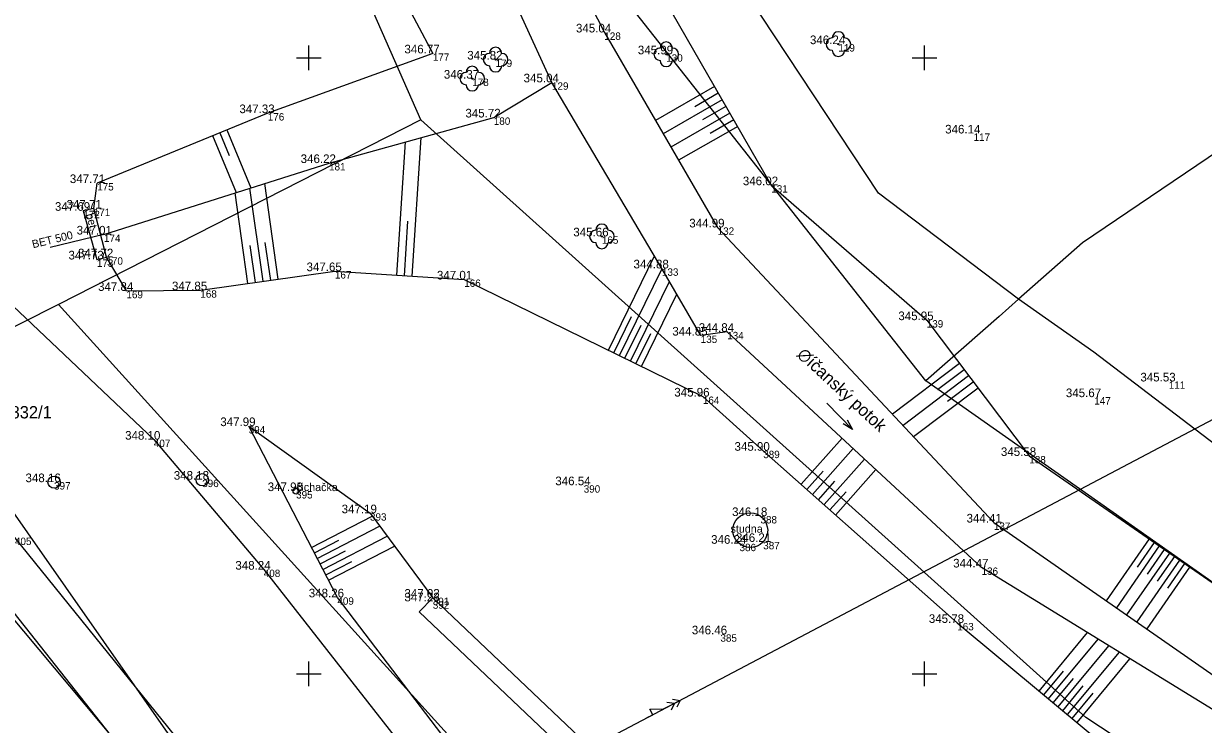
# Model space of a CAD drawing. Extents: x -614046 to -613877, y -1156755 to -1156623.
# Drawn here: x -614009.26 to -613970.95, y -1156701.64 to -1156678.89 of the extents above; entities that cross this region are included whole.
import ezdxf

# ---------------------------------------------------------------- set-up
doc = ezdxf.new("R2010")
doc.units = 0
for name, color, linetype in [('1-bod', 7, 'Continuous'), ('10-silnice', 7, 'Continuous'), ('11-zpevněné plochy', 7, 'Continuous'), ('14-terénní hrany', 7, 'Continuous'), ('15-šrafy', 7, 'Continuous'), ('16-vodní tok', 7, 'Continuous'), ('2-bod výška', 7, 'Continuous'), ('22-stromy', 7, 'Continuous'), ('27-kanalizace značky', 7, 'Continuous'), ('3-bod číslo', 7, 'Continuous'), ('31-plynovod značky', 7, 'Continuous'), ('32-elekrické vedení', 7, 'Continuous'), ('40-popisy povrchů', 7, 'Continuous'), ('45-popis vodní tok', 7, 'Continuous'), ('50-hranice parcel KN', 7, 'Continuous'), ('61-hektarová síť', 7, 'Continuous'), ('7-plot', 7, 'Continuous')]:
    doc.layers.add(name, color=color, linetype=linetype)

# ---------------------------------------------------------------- blocks, each defined once
blk = doc.blocks.new('3.13_1')
at = {"layer": '22-stromy'}
blk.add_circle((0, 0), 0.05, dxfattribs=at)
for centre, start, end in [((0, 0.5), 0, 180), ((-0.5, 0), 90, 270), ((0.5, 0), 270, 90), ((0, -0.5), 180, 0)]:
    blk.add_arc(centre, 0.5, start, end, dxfattribs=at)
blk = doc.blocks.new('6.20_1')
at = {"layer": '27-kanalizace značky'}
blk.add_circle((0, 0), 0.5, dxfattribs=at)
blk = doc.blocks.new('8.02')
at = {"layer": '45-popis vodní tok'}
blk.add_line((-3, 0), (0, 0), dxfattribs=at)
blk.add_lwpolyline([(-0.876, 0.23), (0, 0), (-0.876, -0.23)], dxfattribs=at)
blk = doc.blocks.new('6.14B_1')
at = {"layer": '31-plynovod značky'}
blk.add_circle((0, 0), 0.25, dxfattribs=at)
blk = doc.blocks.new('6.61_1')
at = {"layer": '32-elekrické vedení'}
for points in [[(-3, 0), (-2.5, 0), (-2.5, 0.5), (-1.5, 0), (0, 0)], [(-1, 0.375), (-0.5, 0), (-1, -0.375)], [(-0.5, 0.375), (0, 0), (-0.5, -0.375)]]:
    blk.add_lwpolyline(points, dxfattribs=at)
blk = doc.blocks.new('POINT_DISPLAY')
blk.add_line((0, 0), (0, 0))

msp = doc.modelspace()

# ---------------------------------------------------------------- linework, layer by layer
at = {"layer": '10-silnice'}
for points in [[(-614040.86, -1156670.12), (-614026.04, -1156676.19), (-614020.49, -1156678.89), (-614017.81, -1156680.62), (-614014.97, -1156682.84), (-614010.02, -1156687.67), (-614005.03, -1156692.4), (-614001.46, -1156696.62), (-613996.56, -1156702.86), (-613991.22, -1156709.86), (-613982.03, -1156721.02), (-613980.56, -1156722.02), (-613978.09, -1156724.42), (-613976.34, -1156726.49), (-613975.01, -1156727.5), (-613973.5, -1156728.21), (-613971.99, -1156728.45), (-613970.47, -1156728.44), (-613968.47, -1156728.24), (-613968.3, -1156728.73), (-613958.25, -1156725.06), (-613953.29, -1156723.55)], [(-613998.81, -1156737.86), (-613991.24, -1156735.67), (-613989.47, -1156735.13), (-613988.16, -1156734.5), (-613987.29, -1156733.62), (-613986.54, -1156732.34), (-613986.06, -1156731.07), (-613985.73, -1156729.66), (-613985.61, -1156728.49), (-613985.69, -1156727.41), (-613986.15, -1156725.89), (-613987.36, -1156723.48), (-613995.06, -1156713.22), (-614002.8, -1156703.92), (-614009.54, -1156695.58), (-614011.63, -1156693.4), (-614020.17, -1156685.74), (-614023.41, -1156683.58), (-614026.53, -1156682.03), (-614044.45, -1156674.63)]]:
    msp.add_lwpolyline(points, dxfattribs=at)
at = {"layer": '11-zpevněné plochy'}
msp.add_line((-614006.57, -1156686.48), (-614006.98, -1156684.9), dxfattribs=at)
for points in [[(-614006.98, -1156684.9), (-614007.32, -1156684.97), (-614006.88, -1156686.55), (-614006.57, -1156686.48)], [(-614006.65, -1156685.74), (-614008.401, -1156686.16)]]:
    msp.add_lwpolyline(points, dxfattribs=at)
msp.add_circle((-613985.66, -1156695.34), 0.564, dxfattribs=at)
at = {"layer": '14-terénní hrany'}
for p, q in [((-613993.99, -1156681.94), (-613992.1, -1156680.8)), ((-613999.34, -1156683.42), (-613993.99, -1156681.94)), ((-614006.65, -1156685.74), (-613999.34, -1156683.42)), ((-614006.98, -1156684.9), (-614006.87, -1156684.07)), ((-614005.92, -1156687.57), (-614006.57, -1156686.48)), ((-613998.01, -1156694.79), (-613995.97, -1156697.53))]:
    msp.add_line(p, q, dxfattribs=at)
for points in [[(-614004.4, -1156659.13), (-614004.3, -1156663.09), (-614002.61, -1156666.66), (-614001.67, -1156667.48), (-614000.1, -1156670.92), (-613999.15, -1156673.88), (-613995.97, -1156679.86), (-614001.33, -1156681.8), (-614006.87, -1156684.07)], [(-613997.04, -1156660.09), (-613993.56, -1156668.05), (-613988.66, -1156677.73), (-613984.98, -1156684.14), (-613979.93, -1156688.52), (-613976.6, -1156692.93), (-613968.24, -1156698.72), (-613963.28, -1156701.99), (-613959.08, -1156705.39), (-613955.46, -1156707.77), (-613951.07, -1156711.08), (-613944.86, -1156716.28)], [(-614005.92, -1156687.57), (-614003.52, -1156687.55), (-613999.15, -1156686.93), (-613994.95, -1156687.2), (-613987.2, -1156691), (-613985.24, -1156692.76), (-613978.94, -1156698.35), (-613973.2, -1156703.12), (-613965.66, -1156708.33)], [(-613957.9, -1156720.91), (-613960.99, -1156718.37), (-613971.77, -1156722.19), (-613979.82, -1156720.78), (-613982.37, -1156717.47), (-613989.67, -1156708.83), (-613995.3, -1156702.47), (-613999.07, -1156697.52), (-614001.95, -1156691.96)], [(-614001.95, -1156691.96), (-613998.01, -1156694.79)]]:
    msp.add_lwpolyline(points, dxfattribs=at)
at = {"layer": '15-šrafy'}
for p, q in [((-613986.82, -1156680.93), (-613988.74, -1156682.04)), ((-613986.57, -1156681.37), (-613988.49, -1156682.47)), ((-613986.7, -1156681.15), (-613987.46, -1156681.59)), ((-613986.32, -1156681.8), (-613988.24, -1156682.9)), ((-613986.45, -1156681.58), (-613987.21, -1156682.02)), ((-613986.07, -1156682.23), (-613987.99, -1156683.33)), ((-613986.2, -1156682.02), (-613986.96, -1156682.46)), ((-614003.12, -1156682.53), (-614002.36, -1156684.38)), ((-614002.89, -1156682.44), (-614002.58, -1156683.18)), ((-614002.66, -1156682.34), (-614001.88, -1156684.23)), ((-613996.64, -1156687.09), (-613996.35, -1156682.59)), ((-613997.14, -1156687.06), (-613996.86, -1156682.73)), ((-614000.99, -1156687.19), (-614001.43, -1156684.08)), ((-614001.98, -1156687.33), (-614002.39, -1156684.39)), ((-614001.48, -1156687.26), (-614001.91, -1156684.24)), ((-613996.89, -1156687.08), (-613996.78, -1156685.31)), ((-614001.73, -1156687.3), (-614001.9, -1156686.1)), ((-614001.23, -1156687.23), (-614001.41, -1156686)), ((-613990.27, -1156689.495), (-613988.769, -1156686.435)), ((-613989.911, -1156689.671), (-613988.526, -1156686.847)), ((-613989.552, -1156689.847), (-613988.285, -1156687.264)), ((-613989.192, -1156690.023), (-613988.044, -1156687.681)), ((-613990.09, -1156689.583), (-613989.513, -1156688.406)), ((-613989.731, -1156689.759), (-613989.201, -1156688.678)), ((-613989.372, -1156689.935), (-613988.889, -1156688.95)), ((-613978.87, -1156689.93), (-613981.04, -1156691.57)), ((-613978.57, -1156690.33), (-613980.7, -1156691.94)), ((-613978.72, -1156690.13), (-613979.58, -1156690.78)), ((-613978.42, -1156690.53), (-613979.26, -1156691.16)), ((-613978.26, -1156690.73), (-613980.36, -1156692.31)), ((-613984.01, -1156693.85), (-613982.68, -1156692.35)), ((-613983.64, -1156694.18), (-613982.32, -1156692.69)), ((-613983.26, -1156694.51), (-613981.95, -1156693.03)), ((-613982.89, -1156694.85), (-613981.58, -1156693.37)), ((-613983.82, -1156694.02), (-613983.29, -1156693.42)), ((-613983.45, -1156694.35), (-613982.92, -1156693.75)), ((-613983.08, -1156694.68), (-613982.55, -1156694.09)), ((-613999.909, -1156695.9), (-613997.942, -1156694.881)), ((-613999.725, -1156696.255), (-613997.7, -1156695.206)), ((-613999.817, -1156696.078), (-613999.019, -1156695.664)), ((-613999.541, -1156696.611), (-613997.458, -1156695.532)), ((-613972.709, -1156695.625), (-613974.098, -1156697.629)), ((-613999.633, -1156696.433), (-613998.811, -1156696.007)), ((-613999.357, -1156696.966), (-613997.216, -1156695.857)), ((-613972.38, -1156695.852), (-613973.769, -1156697.858)), ((-613972.051, -1156696.08), (-613973.441, -1156698.086)), ((-613972.545, -1156695.739), (-613973.1, -1156696.541)), ((-613972.216, -1156695.966), (-613972.771, -1156696.769)), ((-613999.449, -1156696.788), (-613998.604, -1156696.351)), ((-613971.723, -1156696.308), (-613973.112, -1156698.314)), ((-613971.887, -1156696.194), (-613972.443, -1156696.997)), ((-613971.558, -1156696.422), (-613972.114, -1156697.225)), ((-613971.394, -1156696.536), (-613972.784, -1156698.543)), ((-613976.281, -1156700.56), (-613974.707, -1156698.666)), ((-613975.973, -1156700.815), (-613974.363, -1156698.877)), ((-613975.666, -1156701.071), (-613974.018, -1156699.089)), ((-613975.358, -1156701.327), (-613973.674, -1156699.3)), ((-613975.05, -1156701.582), (-613973.33, -1156699.512)), ((-613976.127, -1156700.687), (-613975.49, -1156699.921)), ((-613975.82, -1156700.943), (-613975.168, -1156700.159)), ((-613975.512, -1156701.199), (-613974.846, -1156700.397)), ((-613975.204, -1156701.454), (-613974.523, -1156700.635))]:
    msp.add_line(p, q, dxfattribs=at)
at = {"layer": '16-vodní tok'}
for points in [[(-614001.52, -1156651.1), (-613998.11, -1156660.56), (-613996.01, -1156668.21), (-613990.4, -1156679.18), (-613986.72, -1156685.51), (-613977.75, -1156695.09), (-613969.35, -1156700.93), (-613963.95, -1156705.16), (-613955.95, -1156708.89), (-613951.7, -1156712.2), (-613945.56, -1156718.87), (-613945.478, -1156720.252)], [(-613947.4, -1156720.89), (-613951.41, -1156714.98), (-613956.19, -1156710.22), (-613963.8, -1156706.47), (-613969.59, -1156701.81), (-613978.15, -1156696.55), (-613986.41, -1156688.9), (-613987.27, -1156689.02), (-613988.53, -1156686.84), (-613992.1, -1156680.8), (-613997.89, -1156668.2), (-613999.34, -1156662.5), (-614003.52, -1156652.97)]]:
    msp.add_lwpolyline(points, dxfattribs=at)
at = {"layer": '32-elekrické vedení'}
for points in [[(-613977.94, -1156741.03), (-614000.64, -1156707.56), (-614022.4, -1156676.44), (-614038.357, -1156667.025)], [(-614000.64, -1156707.56), (-613951.83, -1156681.82)]]:
    msp.add_lwpolyline(points, dxfattribs=at)
at = {"layer": '50-hranice parcel KN'}
for points in [[(-613996.36, -1156682.02), (-614004.36, -1156663.86)], [(-613981.5, -1156684.4), (-613992.03, -1156668.46)], [(-613979.96, -1156690.49), (-613994.87, -1156671.57)], [(-613955.27, -1156672.74), (-613974.87, -1156686.01)], [(-613996.36, -1156682.02), (-614008.13, -1156688.01)], [(-613974.76, -1156701.42), (-613996.36, -1156682.02)], [(-613976.95, -1156687.84), (-613981.5, -1156684.4)], [(-613974.87, -1156686.01), (-613976.95, -1156687.84)], [(-614008.13, -1156688.01), (-614010.58, -1156689.25)], [(-614008.13, -1156688.01), (-613987.63, -1156710.64)], [(-613976.95, -1156687.84), (-613977.58, -1156688.4)], [(-613974.5, -1156689.56), (-613976.95, -1156687.84)], [(-613977.58, -1156688.4), (-613979.96, -1156690.49)], [(-613943.81, -1156712.94), (-613974.5, -1156689.56)], [(-613947.86, -1156713.04), (-613979.96, -1156690.49)], [(-614013.75, -1156693.26), (-614005.78, -1156702.78)], [(-613954.79, -1156714.58), (-613974.76, -1156701.42)]]:
    msp.add_lwpolyline(points, dxfattribs=at)
at = {"layer": '61-hektarová síť'}
for points in [[(-614000, -1156680.4), (-614000, -1156680), (-614000, -1156679.6)], [(-613980, -1156680.4), (-613980, -1156680), (-613980, -1156679.6)], [(-614000.4, -1156680), (-614000, -1156680), (-613999.6, -1156680)], [(-613980.4, -1156680), (-613980, -1156680), (-613979.6, -1156680)], [(-614000, -1156700.4), (-614000, -1156700), (-614000, -1156699.6)], [(-613980, -1156700.4), (-613980, -1156700), (-613980, -1156699.6)], [(-614000.4, -1156700), (-614000, -1156700), (-613999.6, -1156700)], [(-613980.4, -1156700), (-613980, -1156700), (-613979.6, -1156700)]]:
    msp.add_lwpolyline(points, dxfattribs=at)
at = {"layer": '7-plot'}
for points in [[(-614025.62, -1156687.36), (-614021.23, -1156686.11), (-614012.67, -1156694.12), (-614005.8, -1156702.8), (-613992.19, -1156725.24), (-613995.31, -1156726.13)], [(-613996.41, -1156697.99), (-613995.97, -1156697.53)], [(-613995.97, -1156697.53), (-613982.98, -1156709.87), (-613978.43, -1156714.12), (-613972.48, -1156720.16)], [(-613996.41, -1156697.99), (-613983.42, -1156710.33), (-613978.87, -1156714.58), (-613972.93, -1156720.61)]]:
    msp.add_lwpolyline(points, dxfattribs=at)

# ---------------------------------------------------------------- block references
at = {"layer": '1-bod'}
for p in [(-613990.4, -1156679.18), (-613982.8, -1156679.56), (-613995.97, -1156679.86), (-613988.39, -1156679.89), (-613993.93, -1156680.06), (-613994.69, -1156680.68), (-613992.1, -1156680.8), (-614001.33, -1156681.8), (-613993.99, -1156681.94), (-613978.41, -1156682.46), (-613999.34, -1156683.42), (-614006.87, -1156684.07), (-613984.98, -1156684.14), (-614007.32, -1156684.97), (-614006.98, -1156684.9), (-614006.65, -1156685.74), (-613986.72, -1156685.51), (-613990.48, -1156685.8), (-614006.57, -1156686.48), (-614006.88, -1156686.55), (-613988.53, -1156686.84), (-613999.15, -1156686.93), (-613994.95, -1156687.2), (-614005.92, -1156687.57), (-614003.52, -1156687.55), (-613979.93, -1156688.52), (-613987.27, -1156689.02), (-613986.41, -1156688.9), (-613972.07, -1156690.51), (-613987.2, -1156691), (-613974.49, -1156691.02), (-614001.95, -1156691.96), (-614005.03, -1156692.4), (-613985.24, -1156692.76), (-613976.6, -1156692.93), (-614008.27, -1156693.78), (-614003.46, -1156693.7), (-614000.41, -1156694.07), (-613991.07, -1156693.88), (-613998.01, -1156694.79), (-613985.33, -1156694.88), (-613977.75, -1156695.09), (-613986.01, -1156695.78), (-613985.24, -1156695.72), (-614001.46, -1156696.62), (-613978.15, -1156696.55), (-613999.07, -1156697.52), (-613995.97, -1156697.53), (-613995.97, -1156697.65), (-613978.94, -1156698.35), (-613986.63, -1156698.72)]:
    msp.add_blockref('POINT_DISPLAY', p, dxfattribs=at)
at = {"layer": '22-stromy', "xscale": 0.4, "yscale": 0.4000000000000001}
for p in [(-613982.8, -1156679.56), (-613988.39, -1156679.89), (-613993.93, -1156680.06), (-613994.69, -1156680.68), (-613990.48, -1156685.8)]:
    msp.add_blockref('3.13_1', p, dxfattribs=at)
at = {"layer": '27-kanalizace značky', "xscale": 0.4, "yscale": 0.4000000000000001}
for p in [(-614008.27, -1156693.78), (-614003.46, -1156693.7)]:
    msp.add_blockref('6.20_1', p, dxfattribs=at)
at = {"layer": '31-plynovod značky', "xscale": 0.4, "yscale": 0.4000000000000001}
msp.add_blockref('6.14B_1', (-614000.41, -1156694.07), dxfattribs=at)
at = {"layer": '32-elekrické vedení', "xscale": 0.4, "yscale": 0.4000000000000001, "rotation": 27.804965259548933}
msp.add_blockref('6.61_1', (-613987.943, -1156700.864), dxfattribs=at)
at = {"layer": '45-popis vodní tok', "xscale": 0.39999999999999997, "yscale": 0.39999999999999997, "rotation": -45.60628191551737}
msp.add_blockref('8.02', (-613982.337, -1156692.068), dxfattribs=at)

# ---------------------------------------------------------------- texts
at = {"layer": '2-bod výška'}
for s, p in [('345.04 ', (-613991.322, -1156679.18)), ('346.77 ', (-613996.892, -1156679.86)), ('345.99 ', (-613989.312, -1156679.89)), ('346.24 ', (-613983.722, -1156679.56)), ('345.82 ', (-613994.852, -1156680.06)), ('346.37 ', (-613995.612, -1156680.68)), ('345.04 ', (-613993.022, -1156680.8)), ('347.33 ', (-614002.252, -1156681.8)), ('345.72 ', (-613994.912, -1156681.94)), ('346.14 ', (-613979.332, -1156682.46)), ('346.22 ', (-614000.262, -1156683.42)), ('347.71 ', (-614007.757, -1156684.07)), ('346.02 ', (-613985.902, -1156684.14)), ('347.69 ', (-614008.242, -1156684.97)), ('347.71 ', (-614007.867, -1156684.9)), ('344.99 ', (-613987.642, -1156685.51)), ('347.01 ', (-614007.537, -1156685.74)), ('345.66 ', (-613991.408, -1156685.8)), ('347.73 ', (-614007.802, -1156686.55)), ('347.72 ', (-614007.492, -1156686.48)), ('347.65 ', (-614000.072, -1156686.93)), ('344.88 ', (-613989.452, -1156686.84)), ('347.85 ', (-614004.442, -1156687.55)), ('347.01 ', (-613995.837, -1156687.2)), ('347.84 ', (-614006.842, -1156687.57)), ('345.95 ', (-613980.852, -1156688.52)), ('344.85 ', (-613988.192, -1156689.02)), ('344.84 ', (-613987.332, -1156688.9)), ('345.53 ', (-613972.992, -1156690.51)), ('345.96 ', (-613988.128, -1156691)), ('345.67 ', (-613975.412, -1156691.02)), ('347.99 ', (-614002.872, -1156691.96)), ('348.10 ', (-614005.963, -1156692.4)), ('345.90 ', (-613986.173, -1156692.76)), ('345.58 ', (-613977.522, -1156692.93)), ('348.16 ', (-614009.198, -1156693.78)), ('348.18 ', (-614004.382, -1156693.7)), ('347.98 ', (-614001.332, -1156694.07)), ('346.54 ', (-613991.992, -1156693.88)), ('347.19 ', (-613998.932, -1156694.79)), ('346.18 ', (-613986.252, -1156694.88)), ('344.41 ', (-613978.637, -1156695.09)), ('346.24 ', (-613986.932, -1156695.78)), ('346.21 ', (-613986.127, -1156695.72)), ('348.24 ', (-614002.382, -1156696.62)), ('344.47 ', (-613979.072, -1156696.55)), ('348.26 ', (-613999.998, -1156697.52)), ('347.02 ', (-613996.892, -1156697.53)), ('347.23 ', (-613996.892, -1156697.65)), ('345.78 ', (-613979.862, -1156698.35)), ('346.46 ', (-613987.558, -1156698.72))]:
    msp.add_text(s, height=0.28, dxfattribs=at).set_placement(p)
at = {"layer": '3-bod číslo'}
for s, p in [('128', (-613990.4, -1156679.42)), ('119', (-613982.8, -1156679.8)), ('177', (-613995.97, -1156680.1)), ('130', (-613988.39, -1156680.13)), ('179', (-613993.93, -1156680.3)), ('178', (-613994.69, -1156680.92)), ('129', (-613992.1, -1156681.04)), ('176', (-614001.33, -1156682.04)), ('180', (-613993.99, -1156682.18)), ('117', (-613978.41, -1156682.7)), ('181', (-613999.34, -1156683.66)), ('175', (-614006.87, -1156684.31)), ('131', (-613984.98, -1156684.38)), ('172', (-614007.32, -1156685.21)), ('171', (-614006.98, -1156685.14)), ('174', (-614006.65, -1156685.98)), ('132', (-613986.72, -1156685.75)), ('165', (-613990.48, -1156686.04)), ('170', (-614006.57, -1156686.72)), ('173', (-614006.88, -1156686.79)), ('133', (-613988.53, -1156687.08)), ('167', (-613999.15, -1156687.17)), ('166', (-613994.95, -1156687.44)), ('169', (-614005.92, -1156687.81)), ('168', (-614003.52, -1156687.79)), ('139', (-613979.93, -1156688.76)), ('135', (-613987.27, -1156689.26)), ('134', (-613986.41, -1156689.14)), ('111', (-613972.07, -1156690.75)), ('164', (-613987.2, -1156691.24)), ('147', (-613974.49, -1156691.26)), ('394', (-614001.95, -1156692.2)), ('407', (-614005.03, -1156692.64)), ('389', (-613985.24, -1156693)), ('138', (-613976.6, -1156693.17)), ('397', (-614008.27, -1156694.02)), ('396', (-614003.46, -1156693.94)), ('395', (-614000.41, -1156694.31)), ('390', (-613991.07, -1156694.12)), ('393', (-613998.01, -1156695.03)), ('388', (-613985.33, -1156695.12)), ('137', (-613977.75, -1156695.33)), ('405', (-614009.54, -1156695.82)), ('386', (-613986.01, -1156696.02)), ('387', (-613985.24, -1156695.96)), ('408', (-614001.46, -1156696.86)), ('136', (-613978.15, -1156696.79)), ('409', (-613999.07, -1156697.76)), ('391', (-613995.97, -1156697.77)), ('392', (-613995.97, -1156697.89)), ('163', (-613978.94, -1156698.59)), ('385', (-613986.63, -1156698.96))]:
    msp.add_text(s, height=0.24, dxfattribs=at).set_placement(p)
at = {"layer": '40-popisy povrchů'}
for s, rotation, p in [('bet.', 285.5615, (-614007.242, -1156685.093)), ('BET 500', 13.4767, (-614008.953, -1156686.187))]:
    msp.add_text(s, height=0.26, rotation=rotation, dxfattribs=at).set_placement(p)
for s, p in [('čichačka', (-614000.41, -1156694.07)), ('studna', (-613986.302, -1156695.421))]:
    msp.add_text(s, height=0.26, dxfattribs=at).set_placement(p)
at = {"layer": '45-popis vodní tok'}
msp.add_text('∅íčanský potok', height=0.4, rotation=317.1957, dxfattribs=at).set_placement((-613984.167, -1156689.673))
at = {"layer": '50-hranice parcel KN'}
msp.add_text('1832/1', height=0.4, dxfattribs=at).set_placement((-614009.98, -1156691.71))

doc.saveas('drawing.dxf')
